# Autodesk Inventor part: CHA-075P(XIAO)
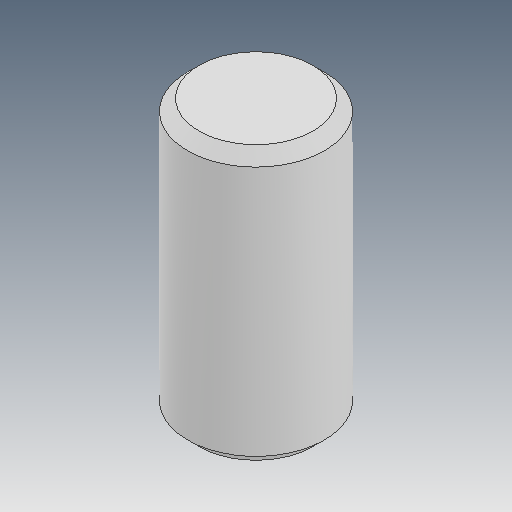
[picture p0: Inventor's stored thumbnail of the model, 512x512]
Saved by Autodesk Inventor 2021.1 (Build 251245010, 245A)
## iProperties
Created: 2021-05
Part Number: CHA-075P(XIAO)
Material: Ogólny
Document SubType Name: Modeling
Designer: user
Density: 1 g/cm^3
Appearance: Domyślna
Author: user
Revision Number: ÈÎºÎ
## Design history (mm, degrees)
feature "µ¹½Ç1"
node "Bryła1"
